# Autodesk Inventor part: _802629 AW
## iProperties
Shininess: 64.0
Length Units: 11269
Angle Units: 11279
Time Units: 11290
Mass Units: 11283
Length Display Precision: 3
Angle Display Precision: 2
Compacted: True
Part Number: _802629 AW
Document SubType Name: Modeling
Created: 2003-07
Material: Standard
Designer: achiml
Density: 0.0
Volumn: 0.0
Area: 0.0
PropertySet Name: Model Information
Control State: 0
Master: False
Checked Out: False
Author: achiml
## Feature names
1. Drehung1 [Revolution]
